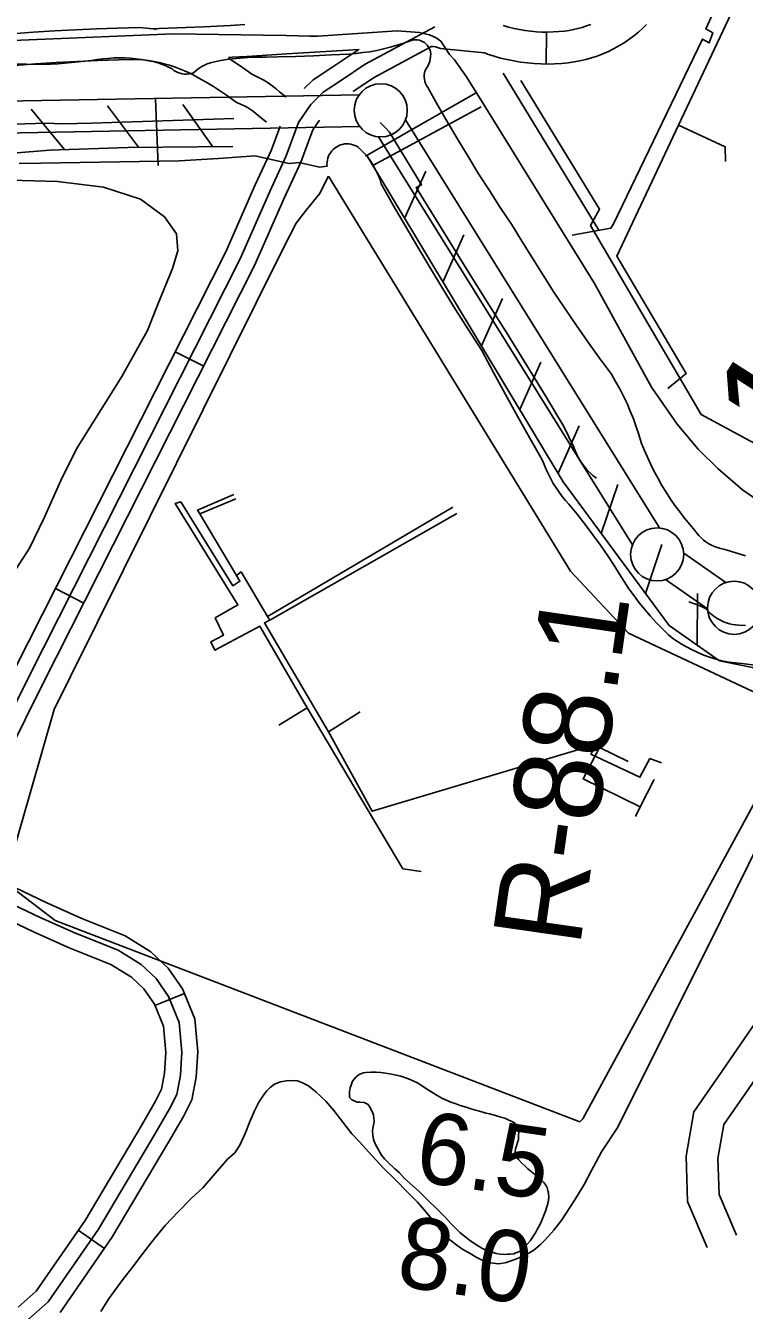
# Model space of a CAD drawing. Extents: x 3704301 to 3742427, y 506229 to 532009.
# Drawn here: x 3714436 to 3715113, y 521733 to 522943 of the extents above; entities that cross this region are included whole.
import ezdxf

# ---------------------------------------------------------------- set-up
doc = ezdxf.new("R2010")
doc.units = 0
for name, color, linetype in [('V-FLOD-BASE', 7, 'Continuous'), ('V-LEVE-TOET', 7, 'Continuous'), ('V-RIVR-RANG', 7, 'Continuous'), ('V-RIVR-RANG-IDEN', 7, 'Continuous'), ('V-ROAD-CNTR', 7, 'Continuous'), ('V-RRAP-FSHR', 7, 'Continuous'), ('V-SITE-OTLN', 7, 'Continuous'), ('V-SITE-VEGE', 7, 'Continuous'), ('V-SURV-IDEN', 7, 'Continuous'), ('V-SURV-LINE', 7, 'Continuous'), ('V-TOPO-SHOR', 7, 'Continuous'), ('V-UTIL-LINE', 7, 'Continuous')]:
    doc.layers.add(name, color=color, linetype=linetype)

msp = doc.modelspace()

# ---------------------------------------------------------------- linework, layer by layer
at = {"layer": 'V-FLOD-BASE'}
msp.add_line((3714470.3, 522850.3), (3714454.5, 522850.8), dxfattribs=at)
for points in [[(3713360.4, 522807.9), (3713523.2, 522807.4), (3713683.2, 522807.8), (3713833.2, 522807.2), (3713927.8, 522807.9), (3713985.1, 522807.1), (3714028.6, 522810), (3714133.7, 522822.6), (3714239.2, 522834.2), (3714375.9, 522848.2), (3714454.5, 522850.8)], [(3714631.9, 522855.1), (3714497.7, 522850.7), (3714470.3, 522850.3)], [(3714973.3, 522516.5), (3714970.4, 522518.8), (3714967.7, 522521.3), (3714965.1, 522523.9), (3714962.7, 522526.7), (3714960.5, 522529.6), (3714958.4, 522532.6), (3714956.5, 522535.8), (3714954.8, 522539), (3714953.3, 522542.4), (3714952, 522545.8), (3714942.6, 522565.3), (3714925.3, 522594), (3714907.8, 522622.7), (3714890.2, 522651.2), (3714872.4, 522679.6), (3714854.5, 522707.9), (3714803.6, 522790.3), (3714808.6, 522792.6), (3714778.4, 522842.4), (3714774.9, 522846), (3714772.4, 522848.5), (3714769.7, 522851.3)], [(3715113.8, 522377.9), (3715107.7, 522378.1), (3715104.7, 522378.4), (3715101.7, 522378.9), (3715098.8, 522379.6), (3715095.9, 522380.4), (3715093.1, 522381.5), (3715090.3, 522382.8), (3715087.7, 522384.2), (3715085.2, 522385.8), (3715082.7, 522387.6), (3715080.4, 522389.5), (3715078.3, 522391.6), (3715076.2, 522393.9), (3715071.1, 522396.3), (3715065.8, 522398.4), (3715060.4, 522400.3)]]:
    msp.add_lwpolyline(points, dxfattribs=at)
at = {"layer": 'V-LEVE-TOET'}
for p, q in [((3714452.9, 522905.9), (3714420.5, 522906.6)), ((3714449.5, 522813), (3714429.6, 522812.7))]:
    msp.add_line(p, q, dxfattribs=at)
for points in [[(3714815.9, 522921.2), (3714814, 522924.2), (3714812.8, 522925.4), (3714811.4, 522926.6), (3714809.9, 522927.5), (3714808.3, 522928.3), (3714806.6, 522928.8), (3714804.9, 522929.2), (3714803.2, 522929.3), (3714801.4, 522929.2), (3714799.7, 522928.9), (3714798, 522928.4), (3714791.8, 522926.2), (3714785.5, 522924.1), (3714779.2, 522922.3), (3714772.8, 522920.7), (3714766.4, 522919.3), (3714759.9, 522918.1), (3714753.4, 522917.2), (3714746.8, 522916.4), (3714740.2, 522915.9), (3714723.5, 522915), (3714706.7, 522914.3), (3714689.9, 522913.7), (3714673.1, 522913.2), (3714662.2, 522913)], [(3714600, 522903.3), (3714597.9, 522901.7), (3714595.8, 522900), (3714593.9, 522898.2), (3714591.8, 522897.6), (3714589.7, 522897.2), (3714587.5, 522897), (3714585.4, 522897), (3714583.2, 522897.3), (3714581.1, 522897.8), (3714579, 522898.5), (3714577.1, 522899.4), (3714575.2, 522900.5), (3714573.5, 522901.8), (3714570.3, 522903.5), (3714567.1, 522905), (3714563.7, 522906.4), (3714560.3, 522907.5), (3714556.9, 522908.5), (3714553.4, 522909.3), (3714549.8, 522909.8), (3714544.7, 522910.7), (3714539.5, 522911.4), (3714534.3, 522911.9), (3714529.1, 522912.2), (3714523.9, 522912.3), (3714518.6, 522912.2), (3714513.4, 522911.8), (3714508.2, 522911.3), (3714503, 522910.6), (3714497.8, 522909.7), (3714481.9, 522908.2), (3714465.9, 522906.8), (3714452.9, 522905.9)], [(3714662.2, 522913), (3714656.3, 522912.8), (3714648.9, 522912.8), (3714641.5, 522912.4), (3714634.1, 522911.8), (3714626.8, 522910.9), (3714619.5, 522909.7), (3714612.3, 522908.2), (3714609.7, 522907.6), (3714607.6, 522906.9), (3714607.6, 522906.9), (3714606.1, 522906.4)], [(3715047.4, 522490.8), (3715043.1, 522497), (3715039, 522503.3), (3715035.1, 522509.7), (3715031.4, 522516.2), (3715027.9, 522522.9), (3715024.5, 522529.6), (3715021.4, 522536.4), (3715018.4, 522543.3), (3715015.6, 522550.3), (3715013.4, 522557.7), (3715010.9, 522565.1), (3715008.2, 522572.5), (3715005.3, 522579.7), (3715002.2, 522586.8), (3714998.8, 522593.9), (3714995.3, 522600.8), (3714991.5, 522607.7), (3714987.5, 522614.4), (3714976.4, 522629.6), (3714965.4, 522645), (3714954.5, 522660.4), (3714943.9, 522676), (3714933.4, 522691.8), (3714923.1, 522707.6), (3714913, 522723.6), (3714903.1, 522739.6), (3714893.3, 522755.8), (3714882.8, 522771.5), (3714872.5, 522787.3), (3714862.4, 522803.2), (3714852.5, 522819.3), (3714842.7, 522835.4), (3714833.1, 522851.7), (3714823.7, 522868), (3714814.4, 522884.4), (3714813.3, 522886.2), (3714812.4, 522888.1), (3714811.7, 522890.1), (3714811.3, 522892.2), (3714811.1, 522894.3), (3714811.1, 522896.4), (3714811.4, 522898.5), (3714812, 522900.5), (3714813.3, 522902.5), (3714814.5, 522904.6), (3714815.5, 522906.8), (3714816.3, 522909), (3714816.8, 522911.4), (3714817.2, 522913.7), (3714817.3, 522916.1), (3714817.1, 522917.9), (3714816.6, 522919.6), (3714815.9, 522921.2)], [(3714606.1, 522906.4), (3714604.7, 522905.8), (3714602.3, 522904.6), (3714600, 522903.3)], [(3714977.2, 522453.5), (3714970.1, 522463.4), (3714962.8, 522473.1), (3714955.3, 522482.6), (3714947.5, 522492), (3714944.3, 522495.7), (3714941.1, 522499.5), (3714938.2, 522503.4), (3714935.4, 522507.5), (3714932.7, 522511.7), (3714930.3, 522515.9), (3714928.1, 522520.3), (3714926, 522524.8), (3714924.1, 522529.4), (3714922.4, 522534), (3714910.7, 522554.4), (3714899.1, 522574.9), (3714887.7, 522595.4), (3714876.4, 522616.1), (3714865.4, 522636.9), (3714853, 522656.2), (3714840.7, 522675.5), (3714828.7, 522694.9), (3714816.7, 522714.5), (3714805, 522734.1), (3714793.4, 522753.9), (3714782, 522773.7), (3714770.7, 522793.6), (3714769.5, 522797.5), (3714768, 522801.4), (3714766.3, 522805.1), (3714764.4, 522808.7), (3714762.3, 522812.3), (3714760.1, 522815.7), (3714757.6, 522819), (3714754.9, 522822.1), (3714752.1, 522825.1), (3714749.2, 522827.9), (3714747.5, 522829), (3714745.7, 522829.8), (3714743.9, 522830.5), (3714742, 522831), (3714740, 522831.2), (3714738, 522831.3), (3714736.1, 522831.2), (3714734.1, 522830.8), (3714732.3, 522830.3), (3714730.4, 522829.5), (3714728.7, 522828.6), (3714727.1, 522827.5), (3714725.6, 522826.3), (3714724.2, 522824.8), (3714723, 522823.3), (3714721.9, 522821.6), (3714721.1, 522819.9), (3714720.4, 522818), (3714719.9, 522816.1), (3714719.6, 522814.2), (3714719.5, 522812.2), (3714719.6, 522810.3)], [(3714683.5, 522812.8), (3714651.8, 522820), (3714617.4, 522817.6), (3714580.1, 522815.2), (3714449.5, 522813)], [(3714719.6, 522810.3), (3714712.6, 522809.5), (3714693.3, 522813.9), (3714684.1, 522812.9), (3714683.5, 522812.8)], [(3715113.9, 522443.5), (3715103.7, 522446.8), (3715093.3, 522449.9), (3715090.4, 522450.5), (3715087.5, 522451.2), (3715084.6, 522452.3), (3715081.8, 522453.5), (3715079.2, 522454.9), (3715076.6, 522456.6), (3715074.2, 522458.4), (3715072, 522460.5), (3715069.9, 522462.6), (3715068, 522465), (3715066.2, 522467.5), (3715061.3, 522473.1), (3715056.5, 522478.9), (3715051.9, 522484.8), (3715047.4, 522490.8)], [(3715122.6, 522340.6), (3715110.4, 522342.1), (3715098.3, 522343.4), (3715093.2, 522344.4), (3715088, 522345.6), (3715083, 522347.1), (3715078, 522348.7), (3715073.1, 522350.6), (3715068.2, 522352.7), (3715063.5, 522354.9), (3715058.8, 522357.4), (3715054.3, 522360), (3715049.8, 522362.8), (3715045.5, 522365.8), (3715041.3, 522369), (3715035.5, 522374.8), (3715029.8, 522380.7), (3715024.3, 522386.8), (3715019, 522393), (3715013.8, 522399.4), (3715008.8, 522405.9), (3715004, 522412.6), (3714999.4, 522419.4), (3714995, 522426.3), (3714990.8, 522433.4), (3714984.1, 522443.5), (3714977.2, 522453.5)]]:
    msp.add_lwpolyline(points, dxfattribs=at)
at = {"layer": 'V-ROAD-CNTR'}
for p, q in [((3714925.9, 522906.6), (3714926.2, 522936.6)), ((3714576.6, 522635.7), (3714603.4, 522622.2)), ((3714463.7, 522412.7), (3714490.5, 522399.1)), ((3714557.4, 522020.3), (3714585.2, 522031.6)), ((3714485.2, 521808.7), (3714509.9, 521791.6))]:
    msp.add_line(p, q, dxfattribs=at)
for points in [[(3714558.7, 522939), (3714555.7, 522939.5), (3714549.5, 522940.2), (3714542.9, 522940.8), (3714522.3, 522940.3), (3714502.4, 522939.7), (3714482.5, 522938.8), (3714462.7, 522937.8), (3714442.8, 522936.5), (3714423, 522935), (3714403.2, 522933.3), (3714383.5, 522931.4)], [(3714821, 522941.5), (3714755.5, 522906.3), (3714733.3, 522891.3), (3714715.9, 522879.9), (3714704.2, 522868.3), (3714692.8, 522851.5), (3714681.2, 522819.9), (3714665.6, 522786.4), (3714637.7, 522723.2), (3714438.2, 522329), (3714405.3, 522262.9)], [(3714642.1, 522943.6), (3714628.6, 522942.8), (3714603.4, 522941.5), (3714578.3, 522940.5), (3714553, 522939.6)], [(3715020.5, 522943.6), (3715017.1, 522940.2), (3715012.9, 522936.5), (3715008.5, 522932.9), (3715004, 522929.5), (3714999.4, 522926.4), (3714994.6, 522923.5), (3714989.6, 522920.8), (3714984.6, 522918.3), (3714979.4, 522916), (3714974.1, 522914), (3714968.8, 522912.3), (3714963.4, 522910.8), (3714957.9, 522909.5), (3714952.3, 522908.5), (3714946.8, 522907.7), (3714940.4, 522907.1), (3714934, 522906.7), (3714927.6, 522906.5), (3714921.1, 522906.6), (3714914.7, 522907), (3714908.3, 522907.5), (3714901.9, 522908.3), (3714895.6, 522909.4), (3714889.3, 522910.6), (3714883.1, 522912.1), (3714876.9, 522913.9), (3714870.7, 522915.8), (3714867.9, 522916.9)], [(3714968.1, 522943.8), (3714964.1, 522942.3), (3714960, 522941), (3714955.9, 522939.8), (3714951.8, 522938.9), (3714947.6, 522938.1), (3714943.3, 522937.5), (3714938, 522937), (3714932.7, 522936.7), (3714927.4, 522936.6), (3714922.1, 522936.6), (3714916.8, 522936.9), (3714911.5, 522937.4), (3714906.2, 522938), (3714901, 522938.9), (3714895.8, 522939.9), (3714890.6, 522941.2), (3714885.5, 522942.6)], [(3714744.2, 522880.5), (3714763.3, 522893.4), (3714818, 522922.9)], [(3714817.8, 522922.9), (3714819.7, 522922.9), (3714821.7, 522922.7), (3714823.5, 522922.1), (3714826.5, 522921), (3714867.9, 522916.9)], [(3714662.5, 522851.8), (3714655.9, 522857.1), (3714652.8, 522859.7), (3714650.2, 522861.7), (3714647.4, 522863.6), (3714644.6, 522865.4), (3714641.7, 522867), (3714638.7, 522868.5), (3714633.8, 522870.6), (3714625.8, 522876.4), (3714619.3, 522880.9), (3714612.6, 522885.2), (3714605.8, 522889.3), (3714598.8, 522893.3), (3714594.2, 522895.9), (3714589.7, 522898.1), (3714585.2, 522900.2), (3714580.5, 522902.1), (3714575.8, 522903.9), (3714571.1, 522905.4), (3714566.2, 522906.8), (3714561.3, 522908), (3714556.4, 522909), (3714551.5, 522909.8), (3714546.5, 522910.4), (3714542, 522910.7), (3714523.1, 522910.3), (3714503.5, 522909.7), (3714484, 522908.9), (3714464.4, 522907.8), (3714444.9, 522906.6), (3714425.4, 522905.1)], [(3714681, 522875.4), (3714674.9, 522880.3), (3714671.7, 522883), (3714667.9, 522885.9), (3714664, 522888.7), (3714659.9, 522891.2), (3714655.6, 522893.6), (3714651.3, 522895.7), (3714648.7, 522896.8), (3714643.1, 522900.9), (3714635.9, 522905.9), (3714628.5, 522910.6), (3714626.5, 522911.9)], [(3714643.9, 522913.7), (3714630.3, 522912.9), (3714626.6, 522912.7)], [(3714643.9, 522913.7), (3714681.8, 522916.2), (3714749.9, 522920.3)], [(3714698.1, 522883.4), (3714706.4, 522891.6), (3714725, 522903.8), (3714749.5, 522920.3)], [(3714419.1, 522257.1), (3714451.6, 522322.3), (3714651.2, 522716.7), (3714679.2, 522780.2), (3714695, 522814.1), (3714706.2, 522844.5), (3714712.4, 522853.6)], [(3714424.8, 522335.8), (3714624.1, 522729.6), (3714651.9, 522792.6), (3714667.3, 522825.6), (3714675.5, 522847.9)], [(3715353.7, 522320.5), (3715352.9, 522305.3), (3715346.8, 522262.6), (3715337.5, 522220.5), (3715329.1, 522198.5), (3715294.3, 522165.7), (3715241.4, 522120.1), (3715173.3, 522059.1), (3715126.2, 522008.4), (3715088.7, 521953.9), (3715065.1, 521920), (3715057.8, 521878.4), (3715059.3, 521835.7), (3715077.7, 521792.4)], [(3715383.4, 522313.3), (3715382.8, 522302.4), (3715376.3, 522257.3), (3715366.3, 522211.9), (3715354.7, 522181.4), (3715314.4, 522143.4), (3715261.2, 522097.6), (3715194.4, 522037.6), (3715149.6, 521989.6), (3715113.4, 521936.9), (3715093.5, 521908.3), (3715087.9, 521876.3), (3715089.1, 521842.3), (3715105.3, 521804.1)], [(3714468.2, 521731.2), (3714516.9, 521801.7), (3714570.2, 521891.4), (3714584.2, 521915.8), (3714592.3, 521931.5), (3714596.3, 521952.8), (3714597.7, 521976.6), (3714594.9, 522007.8), (3714583.4, 522035.9), (3714569.9, 522055.5), (3714553.5, 522070.8), (3714529.5, 522085.7), (3714488.4, 522102.2), (3714455.5, 522116.9), (3714425.3, 522131.2)], [(3714416.3, 522118.8), (3714449.3, 522103.2), (3714482.5, 522088.4), (3714522.7, 522072.3), (3714544.3, 522058.8), (3714558.5, 522045.7), (3714570.1, 522028.8), (3714580.1, 522004.2), (3714582.7, 521976.3), (3714581.4, 521954.6), (3714577.9, 521936.4), (3714571.1, 521923), (3714557.2, 521899), (3714504.2, 521809.8), (3714456.9, 521741.2), (3714437.7, 521724.3)], [(3714428.5, 521736.1), (3714445.6, 521751.3), (3714491.6, 521817.9), (3714544.3, 521906.6), (3714557.9, 521930.1), (3714563.6, 521941.3), (3714566.5, 521956.5), (3714567.6, 521976.1), (3714565.4, 522000.6), (3714556.9, 522021.6), (3714547.1, 522035.8), (3714535.2, 522046.8), (3714515.9, 522058.8), (3714476.7, 522074.6), (3714443, 522089.6), (3714407.3, 522106.5)]]:
    msp.add_lwpolyline(points, dxfattribs=at)
at = {"layer": 'V-RRAP-FSHR'}
for p, q in [((3714472, 522826.4), (3714440.9, 522864.1)), ((3714542, 522828.1), (3714512.7, 522867.1)), ((3714612, 522828.6), (3714583.6, 522868.3)), ((3714792.7, 522761.1), (3714812.5, 522805.7)), ((3714828.8, 522701.1), (3714848.6, 522745.7)), ((3714865, 522641.2), (3714884.8, 522685.8)), ((3714901.1, 522581.2), (3714920.9, 522625.8)), ((3714937.2, 522521.2), (3714957, 522565.9)), ((3714978, 522464.4), (3714993.6, 522510.7)), ((3715019.6, 522408.1), (3715035.1, 522454.3)), ((3715068.4, 522359.2), (3715068.5, 522408.1))]:
    msp.add_line(p, q, dxfattribs=at)
for points in [[(3714630.7, 522828.8), (3714531.9, 522827.8), (3714458.1, 522825.3), (3714393.1, 522820.1), (3714326.2, 522814), (3714264.9, 522806.8), (3714178.1, 522796.9), (3714064.8, 522779.5), (3713986.3, 522775.2), (3713882.2, 522772.6), (3713779.1, 522774.4), (3713686.1, 522774.4), (3713601.1, 522776.1), (3713481.7, 522777.9), (3713355.2, 522782.9)], [(3714756.6, 522821), (3714942.1, 522513.1), (3715041.8, 522377.9), (3715089.2, 522344.7), (3715335, 522294.8)]]:
    msp.add_lwpolyline(points, dxfattribs=at)
at = {"layer": 'V-SITE-OTLN'}
for p, q in [((3714574.8, 522935), (3714390, 522927.3)), ((3714681.1, 522933.2), (3714574.8, 522935)), ((3714785.6, 522937.6), (3714710.8, 522932.7)), ((3714806.8, 522936.3), (3714785.6, 522937.6)), ((3714816.1, 522934.1), (3714806.8, 522936.3)), ((3714822.3, 522931.1), (3714816.1, 522934.1)), ((3714703.1, 522932.8), (3714681.1, 522933.2)), ((3714710.8, 522932.7), (3714703.1, 522932.8)), ((3714826.7, 522927.9), (3714822.3, 522931.1)), ((3714835, 522915.5), (3714826.7, 522927.9)), ((3714839.6, 522910.5), (3714835, 522915.5)), ((3714851, 522894.3), (3714839.6, 522910.5)), ((3714869.3, 522865.2), (3714851, 522894.3)), ((3714971.5, 522699.8), (3714869.3, 522865.2)), ((3715025.4, 522602.2), (3714971.5, 522699.8)), ((3715049.5, 522567.3), (3715025.4, 522602.2)), ((3715069.2, 522543.9), (3715049.5, 522567.3)), ((3715088.2, 522525.3), (3715069.2, 522543.9)), ((3715110.9, 522505.5), (3715088.2, 522525.3)), ((3715134.4, 522489.5), (3715110.9, 522505.5))]:
    msp.add_line(p, q, dxfattribs=at)
msp.add_lwpolyline([(3714721, 522800.8), (3714949, 522429.2), (3715003.6, 522370.7), (3715135.4, 522308.8), (3715154.3, 522270.1), (3714960.7, 521913.5), (3714957.9, 521910.7), (3714463.4, 522100.1), (3714419.6, 522133.7), (3714419.8, 522150.2), (3714462.5, 522298.7), (3714477.9, 522330), (3714677.8, 522732.3), (3714690.5, 522756.7), (3714699.8, 522769), (3714712.5, 522784.3)], close=True, dxfattribs=at)
at = {"layer": 'V-SITE-VEGE'}
for points in [[(3714409.8, 522797.4), (3714465.7, 522795.8), (3714509.1, 522790.5), (3714543.7, 522779.3), (3714566.3, 522762.7), (3714577.6, 522746.7), (3714578.9, 522730.6), (3714574.1, 522714), (3714560.5, 522681.2), (3714550.5, 522655.6), (3714526.2, 522612.2), (3714483.6, 522544.3), (3714468.8, 522514.5), (3714453.4, 522480), (3714439.2, 522450.8), (3714423.2, 522425.8)], [(3714506.6, 521732.3), (3714513.8, 521743.9), (3714527.1, 521762.2), (3714535.2, 521772.5), (3714545.9, 521786.8), (3714555.7, 521799.2), (3714567.2, 521813.1), (3714579.2, 521826.1), (3714591.8, 521838.7), (3714602.4, 521848.5), (3714625.9, 521875.4), (3714632.6, 521881.6), (3714637.4, 521888.6), (3714642.5, 521899.8), (3714647.3, 521911.5), (3714651.1, 521921.2), (3714655.2, 521929.1), (3714659.8, 521935.7), (3714662.9, 521939.8), (3714665.9, 521943), (3714670, 521946), (3714675.7, 521948.3), (3714681.1, 521949.3), (3714687.1, 521949.7), (3714691.8, 521949.2), (3714696.5, 521947.5), (3714702.1, 521944.6), (3714709.1, 521938.9), (3714718.5, 521930), (3714726, 521921.3), (3714742.8, 521899.4), (3714750, 521891.8), (3714758.8, 521882.1), (3714772.6, 521867.3), (3714783.7, 521856.4), (3714795.6, 521844.3), (3714804.8, 521835.2), (3714812.9, 521825.6), (3714821.6, 521815.4), (3714826.9, 521808.5), (3714833.7, 521800.9), (3714840.6, 521795.4), (3714846.6, 521791.3), (3714854.3, 521786.9), (3714860.1, 521783.4), (3714866.5, 521780.3), (3714873.3, 521778.1), (3714881.3, 521777), (3714888.8, 521778.2), (3714898.1, 521781.8), (3714905.9, 521784.9), (3714914.4, 521790), (3714920.6, 521795.1), (3714925.2, 521799.6), (3714933.3, 521808.8), (3714940.9, 521818.6), (3714953.1, 521837.4), (3714961.9, 521851.7), (3714968.7, 521864.8), (3714978.3, 521882.6), (3714993.4, 521905.7), (3715090.8, 522101), (3715168.2, 522257.2)]]:
    msp.add_lwpolyline(points, dxfattribs=at)
at = {"layer": 'V-SURV-LINE'}
for points in [[(3714362.1, 522870.6), (3714750, 522877.6)], [(3714793.5, 522853.9), (3715032.8, 522469.8)], [(3714750.5, 522847.6), (3714362.7, 522840.6)], [(3715007.3, 522453.9), (3714768.1, 522838)], [(3715055.6, 522445.9), (3715095.2, 522418.3)], [(3715078.1, 522393.7), (3715038.5, 522421.2)]]:
    msp.add_lwpolyline(points, dxfattribs=at)
for centre in [(3714770.2, 522862.9), (3715030.6, 522444.9), (3715103.1, 522394.6)]:
    msp.add_circle(centre, 25, dxfattribs=at)
at = {"layer": 'V-TOPO-SHOR'}
for points in [[(3714897, 521885.2), (3714896.9, 521882.7), (3714897.1, 521879.9), (3714897.3, 521878.8), (3714899.9, 521875.1), (3714902.8, 521872.1), (3714906.3, 521869), (3714908.9, 521866.5), (3714911.8, 521864), (3714914.9, 521861.5), (3714917.7, 521859.3), (3714919.8, 521857.4), (3714921.9, 521855.6), (3714923.8, 521853.6), (3714925.7, 521851), (3714926.9, 521848.5), (3714927.7, 521846.1), (3714928.2, 521843.1), (3714928.6, 521839.4), (3714928, 521835.1), (3714927.1, 521831.6), (3714925.4, 521826.7), (3714923.6, 521821.8), (3714921.6, 521817.2), (3714919.6, 521813), (3714917.9, 521810.1), (3714915.9, 521806.3), (3714913.9, 521803), (3714911.3, 521799), (3714908.7, 521796.3), (3714903.7, 521790.5), (3714900.3, 521788.4), (3714897.6, 521787.3), (3714895.6, 521786.5), (3714892.1, 521786.1), (3714889.6, 521786), (3714886.6, 521785.9), (3714883.1, 521786.2), (3714878.9, 521786.8), (3714875.3, 521788), (3714870.4, 521789.4), (3714865.5, 521791.9), (3714860.3, 521794.8), (3714854.9, 521798.5), (3714850.7, 521801.7), (3714844.7, 521806.4), (3714841.4, 521809.6), (3714836.5, 521814.8), (3714831.1, 521820.7), (3714806.2, 521845.4), (3714792.6, 521857.3), (3714787.7, 521862.6), (3714783.3, 521866.3), (3714776.5, 521872.9), (3714773.7, 521875.9), (3714770.9, 521879.3), (3714769.3, 521882), (3714766.4, 521887.3), (3714764.6, 521890.5), (3714763.4, 521894.3), (3714762.6, 521897.9), (3714762.3, 521902.1), (3714762.6, 521904.8), (3714763.3, 521907.7), (3714763.9, 521911.1), (3714763.7, 521914), (3714763.3, 521917.2), (3714762.1, 521920.5), (3714759.9, 521924.6), (3714758.2, 521927), (3714756.4, 521928), (3714754.4, 521928.8), (3714750.5, 521929.2), (3714747.8, 521929.2), (3714742.8, 521931.4), (3714741.1, 521933.2), (3714740.8, 521934.7), (3714740.6, 521936.6), (3714740.8, 521938.9), (3714741, 521940.8), (3714741.5, 521942.7), (3714742.5, 521946.1), (3714743.1, 521948.2), (3714744.7, 521950.7), (3714746.8, 521952.8), (3714748.5, 521954.2), (3714750.5, 521955.5), (3714753.9, 521956.7), (3714756.4, 521957.2), (3714760.7, 521957.5), (3714765.9, 521957.4), (3714770.4, 521957), (3714774.7, 521956.4), (3714780.2, 521955.5), (3714789.1, 521953.6), (3714796.3, 521951.2), (3714804.1, 521947.8), (3714809.3, 521944.7), (3714813.2, 521941.9), (3714818.3, 521938.6), (3714822.3, 521936)], [(3714822.3, 521936), (3714827.8, 521933), (3714831.3, 521931.3), (3714836.2, 521929.3), (3714840.2, 521928), (3714845, 521926.2), (3714850.5, 521924.4), (3714854.9, 521922.9), (3714859.5, 521921.7), (3714861.9, 521920.9), (3714866.2, 521919.8), (3714869.1, 521919), (3714872.7, 521918.1), (3714878.3, 521916.6), (3714883.2, 521915.2), (3714887.2, 521914), (3714890.3, 521912.7), (3714893.2, 521911.3), (3714895.6, 521910), (3714897.1, 521908.7), (3714898.5, 521907.1), (3714899.6, 521904.8), (3714900.2, 521902.7), (3714900.2, 521900.9), (3714900.1, 521898.6), (3714900, 521896.6), (3714899.9, 521894.1), (3714897, 521885.2)]]:
    msp.add_lwpolyline(points, dxfattribs=at)
at = {"layer": 'V-UTIL-LINE'}
for p, q in [((3714975.6, 522750), (3714885.5, 522898)), ((3714560.4, 522811), (3714558.1, 522873.6)), ((3714755.9, 522819.6), (3714859.3, 522879.2)), ((3714763.4, 522811.2), (3714864.9, 522866.1)), ((3714633.6, 522497.2), (3714599.8, 522482.9)), ((3714663.5, 522386.4), (3714838.2, 522489.4)), ((3714665.6, 522383), (3714842, 522483.3)), ((3715014.5, 522207.2), (3715027.9, 522233.1))]:
    msp.add_line(p, q, dxfattribs=at)
for points in [[(3715134.2, 523026.1), (3715050.6, 522848.8), (3715094.7, 522828.6), (3715095.1, 522814.8)], [(3714950.6, 522745.5), (3714987, 522752), (3714989.4, 522756), (3715073.2, 522930), (3715079.5, 522926.4), (3715083.1, 522935.8), (3715076.6, 522939.6), (3715082.1, 522951.7), (3715050.3, 522966.8), (3715047.2, 522964), (3715013.2, 522981.6)], [(3715214.9, 522499.4), (3715072.2, 522576.4), (3714967.9, 522754.4), (3714976.3, 522769.7), (3714902.2, 522891)], [(3715050.6, 522848.8), (3714992.6, 522725.7), (3715057.8, 522615), (3715040.7, 522601.1)], [(3714700.9, 522300.3), (3714656.1, 522377.4), (3714613.9, 522354.6), (3714610, 522362.4), (3714622, 522368.8), (3714614.2, 522385.1), (3714635.5, 522397.3), (3714576.5, 522492.9), (3714581.7, 522494.5), (3714630.7, 522415.4), (3714637.5, 522419.6), (3714634.2, 522425.1), (3714599.8, 522482.9), (3714597.6, 522486.6), (3714631.6, 522501.4)], [(3714634.2, 522425.1), (3714638.6, 522428.3), (3714663.5, 522386.4), (3714665.6, 522383), (3714660.6, 522380.4), (3714721.1, 522277.8), (3714750.7, 522296.7)], [(3714808.2, 522146.4), (3714791, 522149), (3714700.9, 522300.3), (3714674.1, 522284.2)], [(3714721.1, 522277.8), (3714762, 522203), (3714971.6, 522265.5), (3714972.9, 522264.9), (3714976.4, 522263.2), (3715003.4, 522249.8)], [(3714976.4, 522263.2), (3714960.8, 522233.7), (3715014.5, 522207.2), (3715010.2, 522198.1)], [(3714972.9, 522264.9), (3714968.2, 522256.9), (3715014.3, 522235.1), (3715023.6, 522252.6), (3715034.6, 522248.8)]]:
    msp.add_lwpolyline(points, dxfattribs=at)

# ---------------------------------------------------------------- texts
at = {"layer": 'V-RIVR-RANG'}
for s, p in [('6.5', (3714800.7, 521855.3)), ('8.0', (3714783.5, 521756.7))]:
    msp.add_text(s, height=67, rotation=351.6683, dxfattribs=at).set_placement(p)
at = {"layer": 'V-RIVR-RANG-IDEN'}
msp.add_text('R-88.1', height=83, rotation=81.8144, dxfattribs=at).set_placement((3714957.6, 522074.1))
at = {"layer": 'V-SURV-IDEN'}
msp.add_text('197+29.0', height=100, rotation=57.5331, dxfattribs=at).set_placement((3715161.9, 522534.1))

doc.saveas('drawing.dxf')
